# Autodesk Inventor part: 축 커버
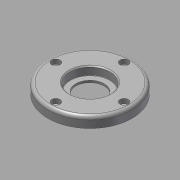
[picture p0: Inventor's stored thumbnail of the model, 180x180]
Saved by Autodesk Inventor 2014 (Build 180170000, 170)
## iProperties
Created: 2015-10
Part Number: 축 커버
Document SubType Name: Modeling
Designer: mdu
Density: 7.86 g/cm^3
Material: 강철, 연강
Appearance: 강철
Mass: 322.464 g
Surface Area: 133.703 cm^2
Volume: 41.026 cm^3
Author: mdu
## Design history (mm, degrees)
sketch "스케치1"
  geometry: C1 r 40 at (0, 0) reference; C2 r 26 at (0, 0) reference; 1 further point
  node "참조1"
  node "참조2"
extrude "돌출1" new body sketch "스케치1" distance "d0" = 10; taper "d1" = 0 deg
extrude "돌출2" join sketch "스케치1" distance "d2" = 3; taper "d3" = 0 deg
hole "구멍1" diameter "d6" = 27; stored, may be unused: countersink angle "d10" = 90 deg, drill point angle "d12" = 118 deg; dims "d4" = 10, "d5" = 10, "d7" = 6, "d8" = 38, "d9" = 8, "d11" = 8
sketch "스케치2"
  geometry: C1 r 20 at (0, 0); 1 further point
  constraints: 1 centre point, 1 coincident
  dimensions: "d13" = 40 diameter of C1
extrude "돌출3" cut sketch "스케치2" distance "d14" = 3; taper "d15" = 0 deg
sketch "스케치3"
  geometry: C1 r 1.621 at (0, 32.5) reference; 1 further point
hole "구멍2" sketch "스케치3" at (0, 32.5) diameter "d16" = 4.5; stored, may be unused: countersink angle "d20" = 90 deg, drill point angle "d22" = 118 deg; dims "d17" = 6, "d18" = 8, "d19" = 4.4, "d21" = 8
fillet "모깎기1" dims "d26" = 3, "d27" = 0.3
chamfer "모따기1" distance "d28" = 1; stored, may be unused: second distance "d29" = 2, angle "d30" = 45 deg
node "솔리드1"
pattern_circular "원형 패턴1" dims angle "d24" = 360 deg
node "참조3"
